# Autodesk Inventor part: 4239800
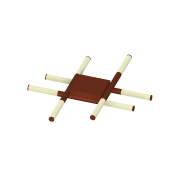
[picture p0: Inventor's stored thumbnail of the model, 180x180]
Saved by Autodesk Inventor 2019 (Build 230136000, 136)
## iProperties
Created: 2020-12
Part Number: 4239800
Material: Generic
Document SubType Name: Modeling
Designer: user
Density: 1 g/cm^3
Appearance: Default
Author: user
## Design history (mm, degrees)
sketch "Sketch1"
  geometry: L1 (-128.698, 37.718)-(51.341, 124.816); L2 (129.729, -37.219)-(-50.31, -124.317); L3 (-50.31, -124.317)-(-128.698, 37.718); L4 (129.729, -37.219)-(51.341, 124.816); 2 further points
  constraints: 8 end point, 1 coincident, 1 parallel
  dimensions: "d76" = 200 distance of L2.start L2.end; "d77" = 180 distance of L2.end L1.start
extrude "Extrusion1" new body sketch "Sketch1" distance "d33" = 40; taper "d34" = 0 deg
node "Sketch2"
workplane "Work Plane1"
sketch "Sketch3"
  geometry: C1 r 17.5 at (-22.5, 17.5); 1 further point
  constraints: 1 centre point
extrude "Extrusion2" join sketch "Sketch3" distance "d37" = 200; taper "d39" = 0 deg; dims "d38" = 100, "d40" = 0
sketch "Sketch4"
  geometry: C1 r 17.5 at (0, 0); 1 further point
  constraints: 1 centre point
extrude "Extrusion3" new body sketch "Sketch4" distance "d41" = 190; taper "d42" = 0 deg
sketch "Sketch5"
  geometry: C1 r 17.5 at (0, 0); 1 further point
  constraints: 1 centre point
extrude "Extrusion4" new body sketch "Sketch5" distance "d43" = 5; taper "d44" = 0 deg
sketch "Sketch6"
  geometry: L1 (-17.5, -17.5)-(-17.5, 22.5) reference; 3 further points
  constraints: 1 horizontal alignment, 2 other
extrude "Extrusion5" new body sketch "Sketch6" distance "d45" = 190; taper "d46" = 0 deg
sketch "Sketch7"
  geometry: C1 r 17.5 at (0, 0); 1 further point
  constraints: 1 centre point
extrude "Extrusion6" new body sketch "Sketch7" distance "d47" = 5; taper "d48" = 0 deg
workplane "Work Plane2"
node "Sketch8"
sketch "Sketch9"
  geometry: C1 r 17.5 at (22.5, -17.5); 2 further points
  constraints: 1 centre point
extrude "Extrusion7" join sketch "Sketch9" distance "d53" = 200; taper "d55" = 0 deg; dims "d54" = 100, "d56" = 0
node "Sketch10"
sketch "Sketch11"
  geometry: C1 r 17.5 at (0, 0); 1 further point
  constraints: 1 centre point
extrude "Extrusion8" new body sketch "Sketch11" distance "d57" = 190; taper "d58" = 0 deg
sketch "Sketch12"
  geometry: C1 r 17.5 at (0, 0); 1 further point
  constraints: 1 centre point
extrude "Extrusion9" new body sketch "Sketch12" distance "d59" = 5; taper "d60" = 0 deg
sketch "Sketch13"
  geometry: C1 r 17.5 at (0, 0); 1 further point
  constraints: 1 centre point
extrude "Extrusion10" new body sketch "Sketch13" distance "d61" = 190; taper "d62" = 0 deg
sketch "Sketch14"
  geometry: C1 r 17.5 at (0, 0); 1 further point
  constraints: 1 centre point
extrude "Extrusion11" new body sketch "Sketch14" distance "d63" = 5; taper "d64" = 0 deg
workplane "Work Plane3"
sketch "Sketch15"
  geometry: C1 r 17.5 at (17.5, -30.783); 1 further point
  constraints: 1 centre point
extrude "Extrusion12" new body sketch "Sketch15" distance "d66" = 180; taper "d68" = 0 deg; dims "d67" = 120, "d69" = 0
sketch "Sketch16"
  geometry: C1 r 17.5 at (0, 0); 1 further point
  constraints: 1 centre point
extrude "Extrusion13" new body sketch "Sketch16" distance "d70" = 190; taper "d71" = 0 deg
sketch "Sketch17"
  geometry: C1 r 17.5 at (0, 0); 1 further point
  constraints: 1 centre point
extrude "Extrusion14" new body sketch "Sketch17" distance "d72" = 190; taper "d73" = 0 deg
sketch "Sketch18"
  geometry: C1 r 17.5 at (0, 0); 1 further point
  constraints: 1 centre point
extrude "Extrusion15" new body sketch "Sketch18" distance "d74" = 5; taper "d75" = 0 deg
node "Sketch19"
feature "Move Body1"
feature "Move Body2"
sketch "Sketch20"
  geometry: C1 r 17.5 at (0, 0); 1 further point
  constraints: 1 centre point
extrude "Extrusion16" new body sketch "Sketch20" distance "d84" = 5; taper "d85" = 0 deg
workplane "Work Plane5"
sketch "Sketch21"
  geometry: C1 r 17.5 at (17.5, -162.5)
  constraints: 1 centre point
extrude "Extrusion17" new body sketch "Sketch21" distance "d90" = 120; taper "d92" = 0 deg; dims "d91" = 180, "d93" = 0
sketch "Sketch22"
  geometry: C1 r 17.5 at (0, 0); 1 further point
  constraints: 1 centre point
extrude "Extrusion18" new body sketch "Sketch22" distance "d94" = 190; taper "d95" = 0 deg
sketch "Sketch23"
  geometry: C1 r 17.5 at (0, 0); 1 further point
  constraints: 1 centre point
extrude "Extrusion19" new body sketch "Sketch23" distance "d96" = 5; taper "d97" = 0 deg
sketch "Sketch24"
  geometry: C1 r 17.5 at (0, 0); 1 further point
  constraints: 1 centre point
extrude "Extrusion20" new body sketch "Sketch24" distance "d98" = 190; taper "d99" = 0 deg
sketch "Sketch25"
  geometry: C1 r 17.5 at (0, 0); 1 further point
  constraints: 1 centre point
extrude "Extrusion21" new body sketch "Sketch25" distance "d100" = 5; taper "d101" = 0 deg
body "Solid1"
body "Solid2"
body "Solid3"
body "Solid4"
body "Solid5"
body "Solid6"
body "Solid7"
body "Solid8"
body "Solid9"
body "Solid10"
body "Solid11"
body "Solid12"
body "Solid13"
body "Solid14"
body "Solid15"
body "Solid16"
body "Solid17"
body "Solid18"
body "Solid19"
other parameters: "d78" = 0, "d79" = 0, "d80" = 13.283, "d81" = 0, "d82" = 0, "d83" = 13.283
